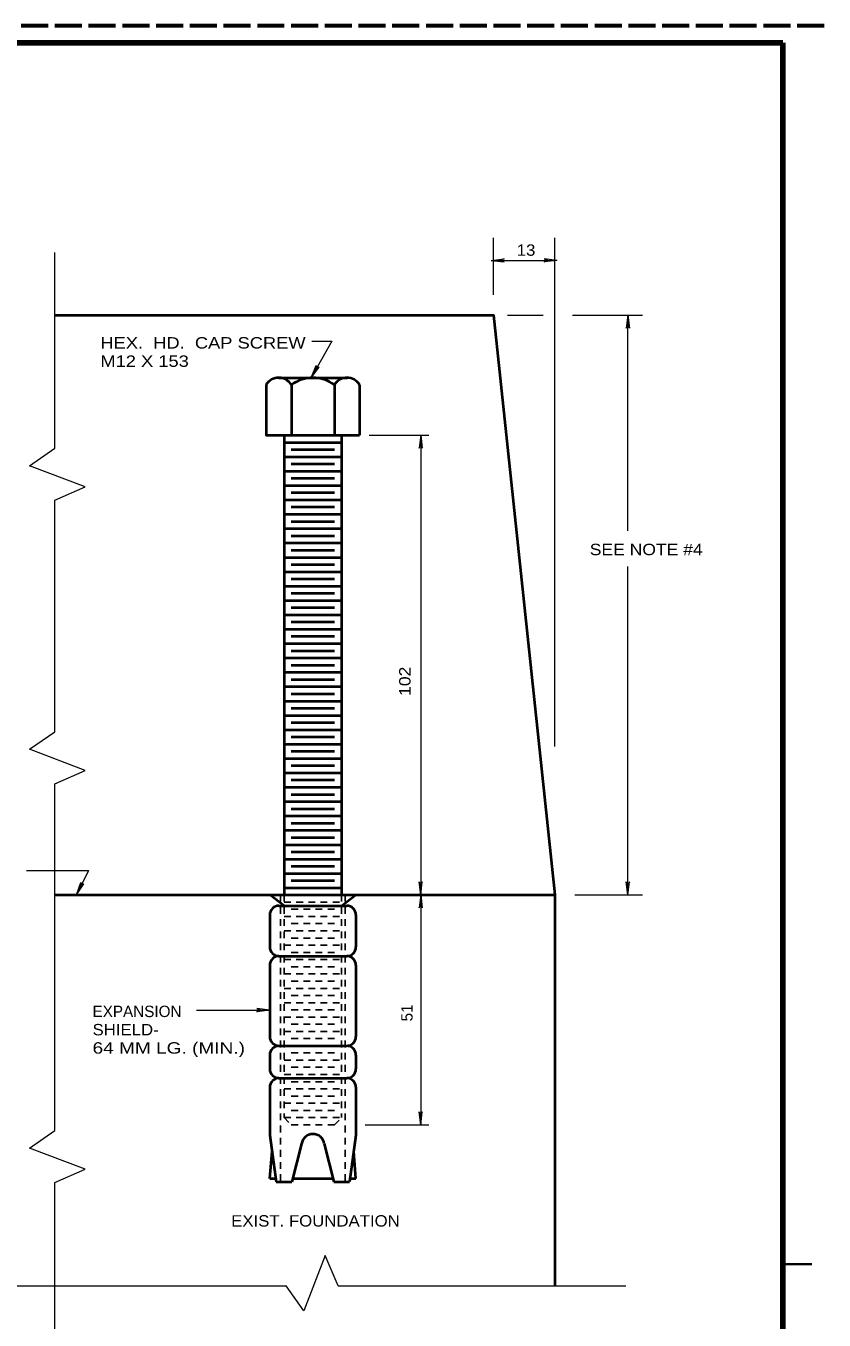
# Model space of a CAD drawing. Extents: x 312583 to 312853, y 144419 to 144586.
# Drawn here: x 312798.5 to 312851.8, y 144499.9 to 144586.2 of the extents above; entities that cross this region are included whole.
import ezdxf

# ---------------------------------------------------------------- set-up
doc = ezdxf.new("R2010")
doc.units = 0
doc.header["$LTSCALE"] = 0.3
doc.linetypes.add('LONG_DASHED', pattern=[7.5, 6, -1.5])
doc.linetypes.add('SHORT_DASHED', pattern=[2.7, 1.5, -1.2])
doc.layers.add('1', color=7, linetype='Continuous', lineweight=40)
doc.layers.add('2', color=7, linetype='Continuous', lineweight=13)

msp = doc.modelspace()

# ---------------------------------------------------------------- linework, layer by layer
at = {"layer": '1', "linetype": 'LONG_DASHED', "lineweight": 60}
msp.add_line((312851.75, 144586.2246), (312583.526, 144586.2246), dxfattribs=at)
msp.add_line((312851.75, 144586.2246), (312583.526, 144586.2246), dxfattribs=at)
at = {"layer": '1', "lineweight": 158}
msp.add_line((312849, 144423.1446), (312849, 144585.0846), dxfattribs=at)
at = {"layer": '1'}
for p, q in [((312815.3776, 144562.7584), (312819.9316, 144562.7584)), ((312816.2209, 144562.2754), (312816.2209, 144558.9251)), ((312819.0882, 144562.2754), (312819.0882, 144558.9251)), ((312820.7672, 144562.2754), (312820.7672, 144558.9251)), ((312815.7379, 144558.9251), (312815.7379, 144528.2584)), ((312819.5712, 144558.9251), (312819.5712, 144528.2584)), ((312815.7379, 144558.4421), (312819.5712, 144558.4421)), ((312815.7379, 144557.4838), (312819.5712, 144557.4838)), ((312816.2132, 144557.9668), (312819.0959, 144557.9668)), ((312815.7379, 144556.5254), (312819.5712, 144556.5254)), ((312816.2132, 144557.0084), (312819.0959, 144557.0084)), ((312815.7379, 144555.5671), (312819.5712, 144555.5671)), ((312816.2132, 144556.0501), (312819.0959, 144556.0501)), ((312815.7379, 144554.6088), (312819.5712, 144554.6088)), ((312816.2132, 144555.0918), (312819.0959, 144555.0918)), ((312816.2132, 144554.1334), (312819.0959, 144554.1334)), ((312815.7379, 144553.6504), (312819.5712, 144553.6504)), ((312816.2132, 144553.1751), (312819.0959, 144553.1751)), ((312815.7379, 144552.6921), (312819.5712, 144552.6921)), ((312816.2132, 144552.2168), (312819.0959, 144552.2168)), ((312815.7379, 144551.7338), (312819.5712, 144551.7338)), ((312816.2132, 144551.2584), (312819.0959, 144551.2584)), ((312815.7379, 144550.7754), (312819.5712, 144550.7754)), ((312816.2132, 144550.3001), (312819.0959, 144550.3001)), ((312815.7379, 144549.8171), (312819.5712, 144549.8171)), ((312815.7379, 144548.8588), (312819.5712, 144548.8588)), ((312816.2132, 144549.3418), (312819.0959, 144549.3418)), ((312815.7379, 144547.9004), (312819.5712, 144547.9004)), ((312816.2132, 144548.3834), (312819.0959, 144548.3834)), ((312815.7379, 144546.9421), (312819.5712, 144546.9421)), ((312816.2132, 144547.4251), (312819.0959, 144547.4251)), ((312815.7379, 144545.9838), (312819.5712, 144545.9838)), ((312816.2132, 144546.4668), (312819.0959, 144546.4668)), ((312816.2132, 144545.5084), (312819.0959, 144545.5084)), ((312815.7379, 144545.0254), (312819.5712, 144545.0254)), ((312816.2132, 144544.5501), (312819.0959, 144544.5501)), ((312815.7379, 144544.0671), (312819.5712, 144544.0671)), ((312816.2132, 144543.5918), (312819.0959, 144543.5918)), ((312815.7379, 144543.1088), (312819.5712, 144543.1088)), ((312816.2132, 144542.6334), (312819.0959, 144542.6334)), ((312815.7379, 144542.1504), (312819.5712, 144542.1504)), ((312816.2132, 144541.6751), (312819.0959, 144541.6751)), ((312815.7379, 144541.1921), (312819.5712, 144541.1921)), ((312815.7379, 144540.2338), (312819.5712, 144540.2338)), ((312816.2132, 144540.7168), (312819.0959, 144540.7168)), ((312815.7379, 144539.2754), (312819.5712, 144539.2754)), ((312816.2132, 144539.7584), (312819.0959, 144539.7584)), ((312815.7379, 144538.3171), (312819.5712, 144538.3171)), ((312816.2132, 144538.8001), (312819.0959, 144538.8001)), ((312815.7379, 144537.3588), (312819.5712, 144537.3588)), ((312816.2132, 144537.8418), (312819.0959, 144537.8418)), ((312816.2132, 144536.8834), (312819.0959, 144536.8834)), ((312815.7379, 144536.4004), (312819.5712, 144536.4004)), ((312816.2132, 144535.9251), (312819.0959, 144535.9251)), ((312815.7379, 144535.4421), (312819.5712, 144535.4421)), ((312816.2132, 144534.9668), (312819.0959, 144534.9668)), ((312815.7379, 144534.4838), (312819.5712, 144534.4838)), ((312816.2132, 144534.0084), (312819.0959, 144534.0084)), ((312815.7379, 144533.5254), (312819.5712, 144533.5254)), ((312816.2132, 144533.0501), (312819.0959, 144533.0501)), ((312815.7379, 144532.5671), (312819.5712, 144532.5671)), ((312815.7379, 144531.6088), (312819.5712, 144531.6088)), ((312816.2132, 144532.0918), (312819.0959, 144532.0918)), ((312815.7379, 144530.6504), (312819.5712, 144530.6504)), ((312816.2132, 144531.1334), (312819.0959, 144531.1334)), ((312815.7379, 144529.6921), (312819.5712, 144529.6921)), ((312816.2132, 144530.1751), (312819.0959, 144530.1751)), ((312815.7379, 144528.7338), (312819.5712, 144528.7338)), ((312816.2132, 144529.2168), (312819.0959, 144529.2168)), ((312800.4429, 144528.2584), (312833.7929, 144528.2584)), ((312815.7379, 144527.5378), (312814.7796, 144528.2584)), ((312819.5712, 144527.5378), (312820.5296, 144528.2584)), ((312833.7929, 144528.2584), (312833.7929, 144502.1841)), ((312815.3929, 144527.5378), (312819.9162, 144527.5378)), ((312814.7796, 144526.9244), (312814.7796, 144524.7931)), ((312820.5296, 144526.9244), (312820.5296, 144524.7931)), ((312814.7796, 144523.5664), (312814.7796, 144518.8054)), ((312815.3929, 144524.1798), (312819.9162, 144524.1798)), ((312820.5296, 144523.5664), (312820.5296, 144518.8054)), ((312814.7796, 144517.5788), (312814.7796, 144516.6511)), ((312815.3929, 144518.1921), (312819.9162, 144518.1921)), ((312820.5296, 144517.5788), (312820.5296, 144516.6511)), ((312815.3929, 144516.0378), (312819.9162, 144516.0378)), ((312814.7796, 144515.4244), (312814.7796, 144512.2274)), ((312820.5296, 144515.4244), (312820.5296, 144512.2274)), ((312814.7796, 144512.2274), (312815.2166, 144509.1148)), ((312816.8956, 144511.6601), (312816.2592, 144509.1148)), ((312818.4136, 144511.6601), (312819.0499, 144509.1148)), ((312820.5296, 144512.2274), (312820.0926, 144509.1148)), ((312814.7796, 144509.3524), (312814.9329, 144511.1388)), ((312820.5296, 144509.3524), (312820.3762, 144511.1388)), ((312814.7796, 144509.3524), (312815.1859, 144509.3524)), ((312815.2166, 144509.1148), (312816.2592, 144509.1148)), ((312816.3206, 144509.3524), (312818.9886, 144509.3524)), ((312819.0499, 144509.1148), (312820.0926, 144509.1148)), ((312820.1232, 144509.3524), (312820.5296, 144509.3524))]:
    msp.add_line(p, q, dxfattribs=at)
at = {"layer": '1', "linetype": 'SHORT_DASHED', "lineweight": 25}
for p, q in [((312815.5002, 144528.2584), (312815.5002, 144509.1148)), ((312815.7379, 144528.2584), (312815.7379, 144513.4004)), ((312816.2132, 144528.2584), (312819.0959, 144528.2584)), ((312819.5712, 144528.2584), (312819.5712, 144513.4004)), ((312819.8089, 144528.2584), (312819.8089, 144509.1148)), ((312815.7379, 144527.7754), (312819.5712, 144527.7754)), ((312816.2132, 144527.3001), (312819.0959, 144527.3001)), ((312815.7379, 144526.8171), (312819.5712, 144526.8171)), ((312816.2132, 144526.3418), (312819.0959, 144526.3418)), ((312815.7379, 144525.8588), (312819.5712, 144525.8588)), ((312816.2132, 144525.3834), (312819.0959, 144525.3834)), ((312815.7379, 144524.9004), (312819.5712, 144524.9004)), ((312816.2132, 144524.4251), (312819.0959, 144524.4251)), ((312815.7379, 144523.9421), (312819.5712, 144523.9421)), ((312815.7379, 144522.9838), (312819.5712, 144522.9838)), ((312816.2132, 144523.4668), (312819.0959, 144523.4668)), ((312815.7379, 144522.0254), (312819.5712, 144522.0254)), ((312816.2132, 144522.5084), (312819.0959, 144522.5084)), ((312815.7379, 144521.0671), (312819.5712, 144521.0671)), ((312816.2132, 144521.5501), (312819.0959, 144521.5501)), ((312815.7379, 144520.1088), (312819.5712, 144520.1088)), ((312816.2132, 144520.5918), (312819.0959, 144520.5918)), ((312816.2132, 144519.6334), (312819.0959, 144519.6334)), ((312815.7379, 144519.1504), (312819.5712, 144519.1504)), ((312816.2132, 144518.6751), (312819.0959, 144518.6751)), ((312815.7379, 144518.1921), (312819.5712, 144518.1921)), ((312816.2132, 144517.7168), (312819.0959, 144517.7168)), ((312815.7379, 144517.2338), (312819.5712, 144517.2338)), ((312816.2132, 144516.7584), (312819.0959, 144516.7584)), ((312815.7379, 144516.2754), (312819.5712, 144516.2754)), ((312816.2132, 144515.8001), (312819.0959, 144515.8001)), ((312815.7379, 144515.3171), (312819.5712, 144515.3171)), ((312815.7379, 144514.3588), (312819.5712, 144514.3588)), ((312816.2132, 144514.8418), (312819.0959, 144514.8418)), ((312815.7379, 144513.4004), (312819.5712, 144513.4004)), ((312815.7379, 144513.4004), (312816.2132, 144512.9251)), ((312816.2132, 144513.8834), (312819.0959, 144513.8834)), ((312819.0959, 144512.9251), (312819.5712, 144513.4004)), ((312816.2132, 144512.9251), (312819.0959, 144512.9251))]:
    msp.add_line(p, q, dxfattribs=at)
at = {"layer": '1', "lineweight": 35}
msp.add_line((312849, 144503.6216), (312850.932, 144503.6216), dxfattribs=at)
at = {"layer": '1', "lineweight": 158}
msp.add_lwpolyline([(312616.5, 144423.1446), (312616.5, 144585.0846), (312849, 144585.0846)], dxfattribs=at)
at = {"layer": '1'}
for points in [[(312800.4429, 144566.9214), (312829.6912, 144566.9214), (312833.7929, 144528.2584)], [(312814.5419, 144562.2754), (312814.5419, 144558.9251), (312820.7672, 144558.9251)]]:
    msp.add_lwpolyline(points, dxfattribs=at)
for centre, radius, start, end in [((312815.3814, 144561.7874), 0.9711, 30.17193, 149.82807), ((312817.6546, 144560.3892), 2.3692, 52.76283, 127.23718), ((312819.9277, 144561.7874), 0.9711, 30.17193, 149.82807), ((312815.3929, 144526.9244), 0.6133, 90, 180), ((312819.9162, 144526.9244), 0.6133, 0, 90), ((312815.3929, 144524.7931), 0.6133, 180, 270), ((312819.9162, 144524.7931), 0.6133, 270, 0), ((312815.3929, 144523.5664), 0.6133, 90, 180), ((312819.9162, 144523.5664), 0.6133, 0, 90), ((312815.3929, 144518.8054), 0.6133, 180, 270), ((312819.9162, 144518.8054), 0.6133, 270, 0), ((312815.3929, 144517.5788), 0.6133, 90, 180), ((312819.9162, 144517.5788), 0.6133, 0, 90), ((312815.3929, 144516.6511), 0.6133, 180, 270), ((312819.9162, 144516.6511), 0.6133, 270, 0), ((312815.3929, 144515.4244), 0.6133, 90, 180), ((312819.9162, 144515.4244), 0.6133, 0, 90), ((312817.6546, 144511.5431), 0.7667, 8.93059, 171.06941)]:
    msp.add_arc(centre, radius, start, end, dxfattribs=at)
at = {"layer": '2'}
for p, q in [((312829.6912, 144568.2861), (312829.6912, 144572.0888)), ((312833.7929, 144538.1484), (312833.7929, 144572.0888)), ((312800.4429, 144558.0588), (312800.4429, 144571.1151)), ((312829.5408, 144570.5861), (312830.4071, 144570.6934)), ((312829.5408, 144570.5861), (312830.4071, 144570.4788)), ((312829.6912, 144570.5861), (312833.7929, 144570.5861)), ((312830.4071, 144570.6934), (312830.1311, 144570.5861)), ((312830.4071, 144570.4788), (312830.1311, 144570.5861)), ((312833.0769, 144570.6934), (312833.3529, 144570.5861)), ((312833.9432, 144570.5861), (312833.0769, 144570.6934)), ((312833.0769, 144570.4788), (312833.3529, 144570.5861)), ((312833.9432, 144570.5861), (312833.0769, 144570.4788)), ((312830.6266, 144566.9214), (312833.0109, 144566.9214)), ((312834.9582, 144566.9214), (312839.6272, 144566.9214)), ((312838.6536, 144566.9214), (312838.5462, 144566.0551)), ((312838.6536, 144552.5541), (312838.6536, 144566.9214)), ((312838.6536, 144566.9214), (312838.7609, 144566.0551)), ((312838.5462, 144566.0551), (312838.6536, 144566.3311)), ((312838.7609, 144566.0551), (312838.6536, 144566.3311)), ((312817.5472, 144562.7584), (312817.8769, 144563.5634)), ((312817.5472, 144562.7584), (312818.0686, 144563.4561)), ((312817.8769, 144563.5634), (312817.8386, 144563.2721)), ((312818.0686, 144563.4561), (312817.8386, 144563.2721)), ((312821.4189, 144558.9251), (312825.3826, 144558.9251)), ((312824.8459, 144558.9251), (312824.7386, 144558.0588)), ((312824.8459, 144558.9251), (312824.9532, 144558.0588)), ((312824.7386, 144558.0588), (312824.8459, 144558.3348)), ((312824.9532, 144558.0588), (312824.8459, 144558.3348)), ((312800.4429, 144539.1451), (312800.4429, 144554.5858)), ((312838.6536, 144528.2584), (312838.6536, 144550.1698)), ((312800.4429, 144512.5494), (312800.4429, 144535.6721)), ((312801.8842, 144528.2584), (312802.1756, 144529.0788)), ((312801.8842, 144528.2584), (312802.3672, 144528.9868)), ((312802.1756, 144529.0788), (312802.1449, 144528.7874)), ((312802.3672, 144528.9868), (312802.1449, 144528.7874)), ((312824.7386, 144529.1248), (312824.8459, 144528.8488)), ((312824.8459, 144528.2584), (312824.7386, 144529.1248)), ((312824.9532, 144529.1248), (312824.8459, 144528.8488)), ((312824.8459, 144528.2584), (312824.9532, 144529.1248)), ((312838.5462, 144529.1248), (312838.6536, 144528.8488)), ((312838.6536, 144528.2584), (312838.5462, 144529.1248)), ((312838.7609, 144529.1248), (312838.6536, 144528.8488)), ((312838.6536, 144528.2584), (312838.7609, 144529.1248)), ((312824.8459, 144528.2584), (312824.7386, 144527.3921)), ((312824.8459, 144528.2584), (312824.9532, 144527.3921)), ((312835.1192, 144528.2584), (312839.6272, 144528.2584)), ((312824.7386, 144527.3921), (312824.8459, 144527.6681)), ((312824.9532, 144527.3921), (312824.8459, 144527.6681)), ((312809.8959, 144520.5688), (312814.7796, 144520.5688)), ((312813.9132, 144520.6761), (312814.1892, 144520.5688)), ((312814.7796, 144520.5688), (312813.9132, 144520.6761)), ((312813.9132, 144520.4614), (312814.1892, 144520.5688)), ((312814.7796, 144520.5688), (312813.9132, 144520.4614)), ((312824.7386, 144513.7914), (312824.8459, 144513.5154)), ((312824.8459, 144512.9251), (312824.7386, 144513.7914)), ((312824.9532, 144513.7914), (312824.8459, 144513.5154)), ((312824.8459, 144512.9251), (312824.9532, 144513.7914)), ((312821.1506, 144512.9251), (312825.3826, 144512.9251)), ((312800.4429, 144497.4998), (312800.4429, 144509.0764)), ((312796.8166, 144502.1841), (312815.8759, 144502.1841)), ((312819.3489, 144502.1841), (312838.5309, 144502.1841))]:
    msp.add_line(p, q, dxfattribs=at)
for points in [[(312817.5856, 144565.1964), (312818.9272, 144565.1964), (312817.5472, 144562.7584)], [(312824.8459, 144558.9251), (312824.8459, 144528.2584), (312824.8459, 144512.9251)], [(312800.4429, 144554.5858), (312802.4746, 144555.4674), (312798.7639, 144556.8858), (312800.4429, 144558.0588)], [(312800.4429, 144535.6721), (312802.4746, 144536.5538), (312798.7639, 144537.9721), (312800.4429, 144539.1451)], [(312798.5492, 144529.8914), (312802.6969, 144529.8914), (312801.8842, 144528.2584)], [(312800.4429, 144509.0764), (312802.4746, 144509.9581), (312798.7639, 144511.3764), (312800.4429, 144512.5494)], [(312819.3489, 144502.1841), (312818.4672, 144504.2158), (312817.0489, 144500.5051), (312815.8759, 144502.1841)]]:
    msp.add_lwpolyline(points, dxfattribs=at)

# ---------------------------------------------------------------- texts
for s, width, p in [('13 ', 1.1, (312831.251, 144570.8916)), ('HEX.  HD.  CAP SCREW', 1.2, (312803.4827, 144564.7025)), ('M12 X 153', 1.2, (312803.4827, 144563.4825)), ('SEE NOTE #4', 1.15, (312836.1176, 144550.9193)), ('SHIELD-', 1.1, (312802.9605, 144518.8908)), ('64 MM LG. (MIN.)', 1.25, (312802.9605, 144517.6708)), ('EXIST. FOUNDATION', 1.1, (312812.2063, 144506.1361))]:
    msp.add_text(s, height=0.76, dxfattribs=dict(at, width=width)).set_placement(p)
at = {"layer": '2', "width": 1.15}
msp.add_text('102 ', height=0.76, rotation=90, dxfattribs=at).set_placement((312824.1651, 144541.5324))
at = {"layer": '2'}
msp.add_text('EXPANSION', height=0.76, dxfattribs=at).set_placement((312802.9605, 144520.1108))
msp.add_text('51 ', height=0.76, rotation=90, dxfattribs=at).set_placement((312824.3051, 144519.8215))

doc.saveas('drawing.dxf')
